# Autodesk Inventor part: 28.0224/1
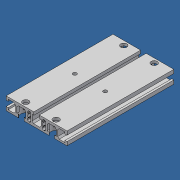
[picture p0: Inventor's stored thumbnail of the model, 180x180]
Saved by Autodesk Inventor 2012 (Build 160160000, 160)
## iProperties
Created: 2007-06
Part Number: 28.0224/1
Material: Aluminum-6061
Document SubType Name: Modeling
Designer: Andy Moles
Density: 2.71 g/cm^3
Description: L = 6.220", MACHINE TO 28.0224/1
Stock Number: 20.0995 PROFILE 90X19
Mass: 304.207 g
Surface Area: 766.203 cm^2
Volume: 112.254 cm^3
Vendor: F
Author: Andy Moles
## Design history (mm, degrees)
sketch "Sketch1"
  geometry: L1 (18.4, -9.5)-(18.4, -5) reference; L2 (17.9, -5)-(15.7, -5) reference; L3 (15.7, -5)-(15.7, 3.5) reference; L4 (15.7, 3.5)-(18, 5.8) reference; L5 (18, 5.8)-(27, 5.8) reference; L6 (27, 5.8)-(29.3, 3.5) reference; L7 (29.3, 3.5)-(29.3, -5) reference; L8 (26.6, -5)-(26.6, -9.5) reference; L9 (45, -9.5)-(26.9, -9.5) reference; L10 (45, -4.1)-(45, -9.5) reference; L11 (45, -4.1)-(42, -4.1) reference; L12 (42, -4.6)-(42, -6.8) reference; L13 (42, -6.8)-(33.5, -6.8) reference; L14 (33.5, -6.8)-(31.2, -4.5) reference; L15 (31.2, -4.5)-(31.2, 4.5) reference; L16 (31.2, 4.5)-(33.5, 6.8) reference; L17 (33.5, 6.8)-(42, 6.8) reference; L18 (42, 4.1)-(45, 4.1) reference; L19 (45, 9.5)-(45, 4.1) reference; L20 (4.4, 9.5)-(45, 9.5) reference; L21 (4.1, 9.5)-(4.1, 5) reference; L22 (4.6, 5)-(6.8, 5) reference; L23 (6.8, 5)-(6.8, -3.5) reference; L24 (6.8, -3.5)-(4.5, -5.8) reference; L25 (4.5, -5.8)-(-4.5, -5.8) reference; L26 (-4.5, -5.8)-(-6.8, -3.5) reference; L27 (-6.8, -3.5)-(-6.8, 5) reference; L28 (-4.1, 5)-(-4.1, 9.5) reference; L29 (-45, 4.1)-(-45, 9.5) reference; L30 (-45, 4.1)-(-42, 4.1) reference; L31 (-42, 4.1)-(-42, 6.8) reference; L32 (-42, 6.8)-(-33.5, 6.8) reference; L33 (-33.5, 6.8)-(-31.2, 4.5) reference; L34 (-31.2, 4.5)-(-31.2, -4.5) reference; L35 (-31.2, -4.5)-(-33.5, -6.8) reference; L36 (-33.5, -6.8)-(-42, -6.8) reference; L37 (-42, -6.8)-(-42, -4.1) reference; L38 (-42, -4.1)-(-45, -4.1) reference; L39 (-45, -9.5)-(-45, -4.1) reference; L40 (-26.6, -9.5)-(-26.6, -5) reference; L41 (-29.3, -5)-(-29.3, 3.5) reference; L42 (-29.3, 3.5)-(-27, 5.8) reference; L43 (-27, 5.8)-(-18, 5.8) reference; L44 (-18, 5.8)-(-15.7, 3.5) reference; L45 (-15.7, 3.5)-(-15.7, -5) reference; L46 (-15.7, -5)-(-17.9, -5) reference; L47 (-18.4, -5)-(-18.4, -9.5) reference; L48 (-18.1, -9.5)-(-18.4, -9.5) reference; L49 (-26.6, -9.5)-(-45, -9.5) reference; L50 (-17.9, -5)-(-18.4, -5) reference; L51 (-26.6, -5)-(-29.3, -5) reference; L52 (-6.8, 5)-(-4.1, 5) reference; L53 (4.1, 5)-(4.6, 5) reference; L54 (-45, 9.5)-(-4.1, 9.5) reference; L55 (4.1, 9.5)-(4.4, 9.5) reference; L56 (29.3, -5)-(26.6, -5) reference; L57 (18.4, -5)-(17.9, -5) reference; L58 (26.9, -9.5)-(26.6, -9.5) reference; L59 (18.4, -9.5)-(-18.1, -9.5) reference; L60 (42, 6.8)-(42, 4.1) reference; L61 (42, -4.1)-(42, -4.6) reference; L62 (-9.354, -2.59)-(-8.993, -2.95); L63 (-10.7, -7)-(-11.3, -7); L64 (-8.7, -3.657)-(-8.7, -5)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; A1 r 2.5 centre (-11, 0) between (-9.333, -1.863) and (-9.333, 1.863); A2 r 1 centre (-9.7, -3.657) between (-8.7, -3.657) and (-8.993, -2.95); A3 r 2 centre (-10.7, -5) between (-10.7, -7) and (-8.7, -5); A4 r 0.5 centre (-9, -2.236) between (-9.333, -1.863) and (-9.354, -2.59); A5 r 1 centre (-12.3, -3.657) between (-13.007, -2.95) and (-13.3, -3.657); A6 r 2.5 centre (-11, 0) between (-12.667, 1.863) and (-12.667, -1.863); A7 r 2 centre (-11.3, -5) between (-13.3, -5) and (-11.3, -7); A8 r 0.5 centre (-13, -2.236) between (-12.646, -2.59) and (-12.667, -1.863); A9 r 0.5 centre (-13, 2.236) between (-12.667, 1.863) and (-12.646, 2.59); A10 r 2 centre (-11.3, 5) between (-11.3, 7) and (-13.3, 5); A11 r 0.5 centre (-9, 2.236) between (-9.354, 2.59) and (-9.333, 1.863); A12 r 1 centre (-9.7, 3.657) between (-8.993, 2.95) and (-8.7, 3.657); A13 r 2 centre (-10.7, 5) between (-8.7, 5) and (-10.7, 7); A14 r 1 centre (-12.3, 3.657) between (-13.3, 3.657) and (-13.007, 2.95); A15 r 1 centre (12.3, 3.657) between (13.007, 2.95) and (13.3, 3.657); A16 r 0.5 centre (13, 2.236) between (12.646, 2.59) and (12.667, 1.863); A17 r 2 centre (11.3, 5) between (13.3, 5) and (11.3, 7); A18 r 0.5 centre (9, 2.236) between (9.333, 1.863) and (9.354, 2.59); A19 r 1 centre (9.7, 3.657) between (8.7, 3.657) and (8.993, 2.95); A20 r 2 centre (10.7, 5) between (10.7, 7) and (8.7, 5); A21 r 1 centre (9.7, -3.657) between (8.993, -2.95) and (8.7, -3.657); A22 r 2.5 centre (11, 0) between (9.333, 1.863) and (9.333, -1.863); A23 r 0.5 centre (9, -2.236) between (9.354, -2.59) and (9.333, -1.863); A24 r 2 centre (10.7, -5) between (8.7, -5) and (10.7, -7); A25 r 2.5 centre (11, 0) between (12.667, -1.863) and (12.667, 1.863); A26 r 0.5 centre (13, -2.236) between (12.667, -1.863) and (12.646, -2.59); A27 r 1 centre (12.3, -3.657) between (13.3, -3.657) and (13.007, -2.95); A28 r 2 centre (11.3, -5) between (11.3, -7) and (13.3, -5)
  constraints: 162 end point, 56 point on circle, 28 centre point, 28 horizontal, 23 vertical, 71 other
extrude "Extrusion1" new body sketch "Sketch1" stored distance "d0" = 158; taper "d1" = 0 deg
sketch "Sketch2"
  geometry: L1 (0, -158)-(36.8, -158) reference; L2 (63.4, -158)-(63.4, 0) reference; L3 (36.8, 0)-(0, 0) reference; 5 further points
  constraints: 2 horizontal alignment, 2 vertical alignment
  dimensions: "d2" = 158 distance of L1.end L3.start (derived); "d5" = 22.5 distance from line of point (40.9, -6.5) L2; "d6" = 67.5 distance from line of point (-4.1, -6.5) L2; "d14" = 6.5 distance from line of point (40.9, -6.5) L3; "d15" = 6.5 distance from line of point (40.9, -151.5) L1
hole "Hole1" sketch "Sketch2" at (40.9, -6.5), (-4.1, -6.5), (-4.1, -151.5), (40.9, -151.5) diameter "d7" = 9; stored, may be unused: countersink angle "d11" = 90 deg, drill point angle "d13" = 118 deg; dims "d8" = 6, "d9" = 15, "d10" = 15.3, "d12" = 8
sketch "Sketch3"
  geometry: 3 further points
  constraints: 2 horizontal alignment
  dimensions: "d16" = 22.5 distance of point (18.4, -79) point (-4.1, -79); "d17" = 22.5 distance of point (40.9, -79) point (18.4, -79)
hole "Hole2" sketch "Sketch3" at (-4.1, -79), (40.9, -79) diameter "d18" = 5.5; stored, may be unused: countersink angle "d22" = 90 deg, drill point angle "d24" = 118 deg; dims "d19" = 6, "d20" = 9, "d21" = 15.3, "d23" = 8
body "Solid1"
